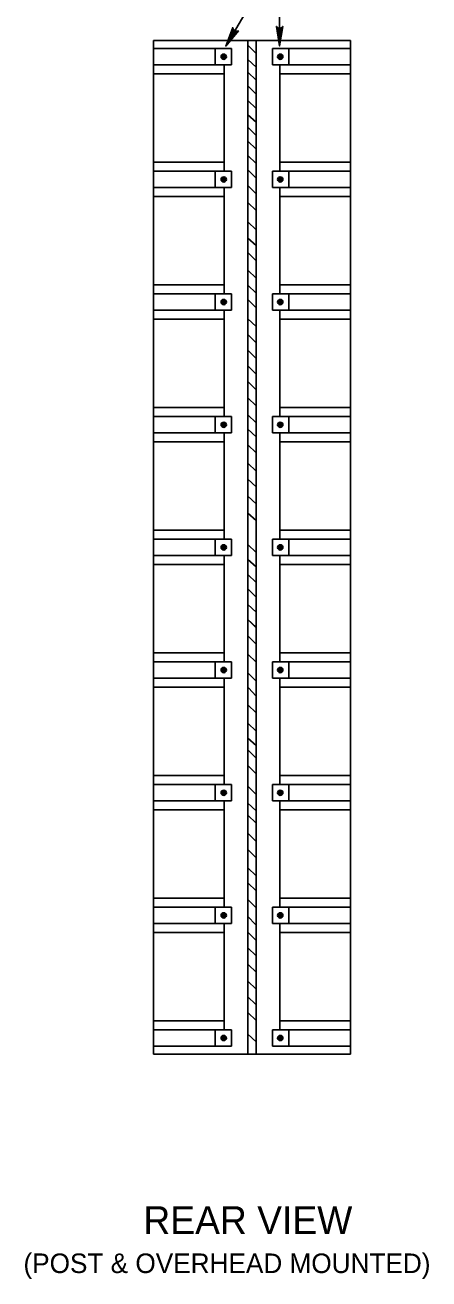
# Model space of a CAD drawing. Extents: x 650495 to 652241, y 298458 to 299646.
# Drawn here: x 650987.1 to 651049.5, y 299351.4 to 299545.2 of the extents above; entities that cross this region are included whole.
import ezdxf

# ---------------------------------------------------------------- set-up
doc = ezdxf.new("R2010")
doc.units = 0
doc.layers.add('2', color=7, linetype='Continuous')
doc.layers.add('3', color=7, linetype='Continuous')

# ---------------------------------------------------------------- blocks, each defined once
blk = doc.blocks.new('RARROW')
at = {"layer": '3'}
blk.add_lwpolyline([(-2.2695, 0.285), (-2.184875, 0.12075), (0, 0), (-2.2695, 0.285), (-2.38575, 0.384625), (0, 0), (-2.183125, -0.108), (-2.262875, -0.2705), (0, 0), (-2.38575, -0.379125), (-2.262875, -0.2705)], dxfattribs=at)

msp = doc.modelspace()

# ---------------------------------------------------------------- linework, layer by layer
at = {"layer": '2'}
for p, q in [((651026.41, 299556.11), (651018.09, 299541.93)), ((651026.41, 299556.11), (651026.4, 299541.95)), ((651006.95, 299386.13), (651006.95, 299542.76)), ((651006.95, 299542.76), (651037.34, 299542.76)), ((651021.52, 299386.13), (651021.52, 299542.76)), ((651022.78, 299540.79), (651021.52, 299542.05)), ((651022.78, 299386.13), (651022.78, 299542.76)), ((651037.34, 299386.13), (651037.34, 299542.76)), ((651017.72, 299541.53), (651006.95, 299541.53)), ((651019, 299541.53), (651016.48, 299541.53)), ((651016.48, 299541.53), (651016.48, 299539.01)), ((651019, 299539.01), (651019, 299541.53)), ((651025.29, 299539.01), (651025.29, 299541.53)), ((651025.29, 299541.53), (651027.81, 299541.53)), ((651026.58, 299541.53), (651037.34, 299541.53)), ((651027.81, 299541.53), (651027.81, 299539.01)), ((651017.72, 299539.01), (651006.95, 299539.01)), ((651016.48, 299539.01), (651019, 299539.01)), ((651017.84, 299522.57), (651017.84, 299539.01)), ((651022.78, 299538.66), (651021.52, 299539.83)), ((651027.81, 299539.01), (651025.29, 299539.01)), ((651026.45, 299522.57), (651026.45, 299539.01)), ((651026.58, 299539.01), (651037.34, 299539.01)), ((651017.84, 299537.61), (651006.95, 299537.61)), ((651022.78, 299536.63), (651021.52, 299537.89)), ((651026.45, 299537.61), (651037.34, 299537.61)), ((651022.78, 299534.5), (651021.52, 299535.76)), ((651022.78, 299532.28), (651021.52, 299533.53)), ((651022.78, 299532.28), (651021.52, 299533.53)), ((651022.78, 299530.15), (651021.52, 299531.31)), ((651022.78, 299528.11), (651021.52, 299529.37)), ((651022.78, 299525.98), (651021.52, 299527.24)), ((651022.78, 299523.76), (651021.52, 299525.02)), ((651017.84, 299523.97), (651006.95, 299523.97)), ((651022.78, 299521.53), (651021.52, 299522.79)), ((651026.45, 299523.97), (651037.34, 299523.97)), ((651017.72, 299522.57), (651006.95, 299522.57)), ((651019, 299522.57), (651016.48, 299522.57)), ((651016.48, 299522.57), (651016.48, 299520.05)), ((651019, 299520.05), (651019, 299522.57)), ((651025.29, 299520.05), (651025.29, 299522.57)), ((651025.29, 299522.57), (651027.81, 299522.57)), ((651026.58, 299522.57), (651037.34, 299522.57)), ((651027.81, 299522.57), (651027.81, 299520.05)), ((651017.72, 299520.05), (651006.95, 299520.05)), ((651016.48, 299520.05), (651019, 299520.05)), ((651017.84, 299503.61), (651017.84, 299520.05)), ((651022.78, 299519.11), (651021.52, 299520.37)), ((651027.81, 299520.05), (651025.29, 299520.05)), ((651026.45, 299503.61), (651026.45, 299520.05)), ((651026.58, 299520.05), (651037.34, 299520.05)), ((651017.84, 299518.66), (651006.95, 299518.66)), ((651022.78, 299516.5), (651021.52, 299517.76)), ((651026.45, 299518.66), (651037.34, 299518.66)), ((651022.78, 299513.5), (651021.52, 299514.75)), ((651022.78, 299511.08), (651021.52, 299512.24)), ((651022.78, 299508.75), (651021.52, 299510.01)), ((651022.78, 299506.04), (651021.52, 299507.3)), ((651017.84, 299505.01), (651006.95, 299505.01)), ((651017.72, 299503.61), (651006.95, 299503.61)), ((651019, 299503.61), (651016.48, 299503.61)), ((651016.48, 299503.61), (651016.48, 299501.1)), ((651019, 299501.1), (651019, 299503.61)), ((651022.78, 299503.72), (651021.52, 299504.98)), ((651025.29, 299501.1), (651025.29, 299503.61)), ((651025.29, 299503.61), (651027.81, 299503.61)), ((651026.45, 299505.01), (651037.34, 299505.01)), ((651026.58, 299503.61), (651037.34, 299503.61)), ((651027.81, 299503.61), (651027.81, 299501.1)), ((651022.78, 299501.49), (651021.52, 299502.75)), ((651017.72, 299501.1), (651006.95, 299501.1)), ((651017.84, 299499.7), (651006.95, 299499.7)), ((651016.48, 299501.1), (651019, 299501.1)), ((651017.84, 299484.66), (651017.84, 299501.1)), ((651022.78, 299498.59), (651021.52, 299499.75)), ((651027.81, 299501.1), (651025.29, 299501.1)), ((651026.45, 299484.66), (651026.45, 299501.1)), ((651026.45, 299499.7), (651037.34, 299499.7)), ((651026.58, 299501.1), (651037.34, 299501.1)), ((651022.78, 299496.07), (651021.52, 299497.33)), ((651022.78, 299493.65), (651021.52, 299494.91)), ((651022.78, 299491.23), (651021.52, 299492.49)), ((651022.78, 299488.81), (651021.52, 299490.07)), ((651017.84, 299486.06), (651006.95, 299486.06)), ((651022.78, 299486.3), (651021.52, 299487.55)), ((651026.45, 299486.06), (651037.34, 299486.06)), ((651017.72, 299484.66), (651006.95, 299484.66)), ((651019, 299484.66), (651016.48, 299484.66)), ((651016.48, 299484.66), (651016.48, 299482.14)), ((651019, 299482.14), (651019, 299484.66)), ((651022.78, 299483.68), (651021.52, 299484.94)), ((651025.29, 299482.14), (651025.29, 299484.66)), ((651025.29, 299484.66), (651027.81, 299484.66)), ((651026.58, 299484.66), (651037.34, 299484.66)), ((651027.81, 299484.66), (651027.81, 299482.14)), ((651017.72, 299482.14), (651006.95, 299482.14)), ((651016.48, 299482.14), (651019, 299482.14)), ((651017.84, 299465.7), (651017.84, 299482.14)), ((651022.78, 299481.55), (651021.52, 299482.71)), ((651027.81, 299482.14), (651025.29, 299482.14)), ((651026.45, 299465.7), (651026.45, 299482.14)), ((651026.58, 299482.14), (651037.34, 299482.14)), ((651017.84, 299480.75), (651006.95, 299480.75)), ((651022.78, 299479.04), (651021.52, 299480.29)), ((651026.45, 299480.75), (651037.34, 299480.75)), ((651022.78, 299476.23), (651021.52, 299477.49)), ((651022.78, 299473.81), (651021.52, 299474.97)), ((651022.78, 299471.19), (651021.52, 299472.36)), ((651022.78, 299468.58), (651021.52, 299469.74)), ((651017.84, 299467.1), (651006.95, 299467.1)), ((651026.45, 299467.1), (651037.34, 299467.1)), ((651017.72, 299465.7), (651006.95, 299465.7)), ((651019, 299465.7), (651016.48, 299465.7)), ((651016.48, 299465.7), (651016.48, 299463.19)), ((651019, 299463.19), (651019, 299465.7)), ((651022.78, 299463.64), (651021.52, 299464.9)), ((651025.29, 299463.19), (651025.29, 299465.7)), ((651025.29, 299465.7), (651027.81, 299465.7)), ((651026.58, 299465.7), (651037.34, 299465.7)), ((651027.81, 299465.7), (651027.81, 299463.19)), ((651017.72, 299463.19), (651006.95, 299463.19)), ((651016.48, 299463.19), (651019, 299463.19)), ((651017.84, 299463.19), (651017.84, 299446.75)), ((651027.81, 299463.19), (651025.29, 299463.19)), ((651026.45, 299463.19), (651026.45, 299446.75)), ((651026.58, 299463.19), (651037.34, 299463.19)), ((651017.84, 299461.79), (651006.95, 299461.79)), ((651022.78, 299461.42), (651021.52, 299462.58)), ((651026.45, 299461.79), (651037.34, 299461.79)), ((651022.78, 299459), (651021.52, 299460.26)), ((651022.78, 299456.77), (651021.52, 299458.03)), ((651022.78, 299454.45), (651021.52, 299455.61)), ((651022.68, 299452.13), (651021.52, 299453.29)), ((651022.78, 299452.13), (651021.52, 299453.29)), ((651022.78, 299449.51), (651021.52, 299450.77)), ((651017.84, 299448.15), (651006.95, 299448.15)), ((651022.78, 299446.7), (651021.52, 299447.96)), ((651026.45, 299448.15), (651037.34, 299448.15)), ((651017.72, 299446.75), (651006.95, 299446.75)), ((651019, 299446.75), (651016.48, 299446.75)), ((651016.48, 299446.75), (651016.48, 299444.23)), ((651019, 299444.23), (651019, 299446.75)), ((651025.29, 299444.23), (651025.29, 299446.75)), ((651025.29, 299446.75), (651027.81, 299446.75)), ((651026.58, 299446.75), (651037.34, 299446.75)), ((651027.81, 299446.75), (651027.81, 299444.23)), ((651017.72, 299444.23), (651006.95, 299444.23)), ((651016.48, 299444.23), (651019, 299444.23)), ((651017.84, 299427.79), (651017.84, 299444.23)), ((651022.78, 299443.8), (651021.52, 299445.06)), ((651027.81, 299444.23), (651025.29, 299444.23)), ((651026.45, 299427.79), (651026.45, 299444.23)), ((651026.58, 299444.23), (651037.34, 299444.23)), ((651017.84, 299442.83), (651006.95, 299442.83)), ((651022.78, 299441.48), (651021.61, 299442.74)), ((651026.45, 299442.83), (651037.34, 299442.83)), ((651022.78, 299438.86), (651021.52, 299440.12)), ((651022.78, 299436.06), (651021.52, 299437.31)), ((651022.78, 299433.83), (651021.52, 299434.99)), ((651022.78, 299431.89), (651021.52, 299433.15)), ((651022.78, 299429.47), (651021.52, 299430.73)), ((651017.84, 299429.19), (651006.95, 299429.19)), ((651017.72, 299427.79), (651006.95, 299427.79)), ((651019, 299427.79), (651016.48, 299427.79)), ((651016.48, 299427.79), (651016.48, 299425.28)), ((651019, 299425.28), (651019, 299427.79)), ((651025.29, 299425.28), (651025.29, 299427.79)), ((651025.29, 299427.79), (651027.81, 299427.79)), ((651026.45, 299429.19), (651037.34, 299429.19)), ((651026.58, 299427.79), (651037.34, 299427.79)), ((651027.81, 299427.79), (651027.81, 299425.28)), ((651022.78, 299426.28), (651021.52, 299427.54)), ((651017.72, 299425.28), (651006.95, 299425.28)), ((651017.84, 299423.88), (651006.95, 299423.88)), ((651016.48, 299425.28), (651019, 299425.28)), ((651017.84, 299408.84), (651017.84, 299425.28)), ((651022.78, 299423.76), (651021.52, 299424.92)), ((651027.81, 299425.28), (651025.29, 299425.28)), ((651026.45, 299408.84), (651026.45, 299425.28)), ((651026.45, 299423.88), (651037.34, 299423.88)), ((651026.58, 299425.28), (651037.34, 299425.28)), ((651022.78, 299421.83), (651021.52, 299423.09)), ((651022.78, 299419.02), (651021.52, 299420.28)), ((651022.78, 299416.5), (651021.52, 299417.76)), ((651022.78, 299413.7), (651021.52, 299414.95)), ((651022.78, 299411.37), (651021.52, 299412.63)), ((651017.84, 299410.24), (651006.95, 299410.24)), ((651017.72, 299408.84), (651006.95, 299408.84)), ((651019, 299408.84), (651016.48, 299408.84)), ((651016.48, 299408.84), (651016.48, 299406.32)), ((651019, 299406.32), (651019, 299408.84)), ((651022.78, 299408.76), (651021.52, 299410.02)), ((651025.29, 299406.32), (651025.29, 299408.84)), ((651025.29, 299408.84), (651027.81, 299408.84)), ((651026.45, 299410.24), (651037.34, 299410.24)), ((651026.58, 299408.84), (651037.34, 299408.84)), ((651027.81, 299408.84), (651027.81, 299406.32)), ((651022.68, 299406.15), (651021.52, 299407.4)), ((651017.72, 299406.32), (651006.95, 299406.32)), ((651017.84, 299404.92), (651006.95, 299404.92)), ((651016.48, 299406.32), (651019, 299406.32)), ((651017.84, 299389.88), (651017.84, 299406.32)), ((651022.68, 299403.82), (651021.52, 299404.98)), ((651027.81, 299406.32), (651025.29, 299406.32)), ((651026.45, 299389.88), (651026.45, 299406.32)), ((651026.45, 299404.92), (651037.34, 299404.92)), ((651026.58, 299406.32), (651037.34, 299406.32)), ((651022.78, 299401.31), (651021.52, 299402.56)), ((651022.78, 299398.79), (651021.61, 299399.95)), ((651022.78, 299396.17), (651021.52, 299397.43)), ((651022.68, 299393.85), (651021.52, 299395.01)), ((651017.84, 299391.28), (651006.95, 299391.28)), ((651022.78, 299391.33), (651021.52, 299392.59)), ((651026.45, 299391.28), (651037.34, 299391.28)), ((651017.72, 299389.88), (651006.95, 299389.88)), ((651016.48, 299389.88), (651019, 299389.88)), ((651016.48, 299387.37), (651016.48, 299389.88)), ((651017.74, 299389.88), (651017.74, 299389.88)), ((651019, 299389.88), (651019, 299387.37)), ((651022.78, 299388.04), (651021.52, 299389.21)), ((651027.81, 299389.88), (651025.29, 299389.88)), ((651025.29, 299389.88), (651025.29, 299387.37)), ((651026.55, 299389.88), (651026.55, 299389.88)), ((651026.58, 299389.88), (651037.34, 299389.88)), ((651027.81, 299387.37), (651027.81, 299389.88)), ((651017.72, 299387.37), (651006.95, 299387.37)), ((651019, 299387.37), (651016.48, 299387.37)), ((651025.29, 299387.37), (651027.81, 299387.37)), ((651026.58, 299387.37), (651037.34, 299387.37)), ((651006.95, 299386.13), (651037.34, 299386.13))]:
    msp.add_line(p, q, dxfattribs=at)
for points in [[(651017.65, 299539.98), (651017.55, 299540.27), (651017.55, 299540.46), (651017.74, 299540.56), (651017.94, 299540.46), (651018.03, 299540.36), (651018.03, 299540.07), (651017.94, 299539.98), (651017.74, 299539.98), (651017.65, 299540.27), (651017.65, 299540.36), (651017.65, 299540.46), (651017.74, 299540.46), (651017.84, 299540.36), (651017.94, 299540.27), (651017.94, 299540.07), (651017.84, 299540.17), (651017.74, 299540.36)], [(651026.65, 299539.98), (651026.75, 299540.27), (651026.75, 299540.46), (651026.55, 299540.56), (651026.36, 299540.46), (651026.26, 299540.36), (651026.26, 299540.07), (651026.36, 299539.98), (651026.55, 299539.98), (651026.65, 299540.27), (651026.65, 299540.36), (651026.65, 299540.46), (651026.55, 299540.46), (651026.45, 299540.36), (651026.36, 299540.27), (651026.36, 299540.07), (651026.45, 299540.17), (651026.55, 299540.36)], [(651017.65, 299521.02), (651017.55, 299521.31), (651017.55, 299521.51), (651017.74, 299521.6), (651017.94, 299521.51), (651018.03, 299521.41), (651018.03, 299521.12), (651017.94, 299521.02), (651017.74, 299521.02), (651017.65, 299521.31), (651017.65, 299521.41), (651017.65, 299521.51), (651017.74, 299521.51), (651017.84, 299521.41), (651017.94, 299521.31), (651017.94, 299521.12), (651017.84, 299521.22), (651017.74, 299521.41)], [(651026.65, 299521.02), (651026.75, 299521.31), (651026.75, 299521.51), (651026.55, 299521.6), (651026.36, 299521.51), (651026.26, 299521.41), (651026.26, 299521.12), (651026.36, 299521.02), (651026.55, 299521.02), (651026.65, 299521.31), (651026.65, 299521.41), (651026.65, 299521.51), (651026.55, 299521.51), (651026.45, 299521.41), (651026.36, 299521.31), (651026.36, 299521.12), (651026.45, 299521.22), (651026.55, 299521.41)], [(651017.65, 299502.07), (651017.55, 299502.36), (651017.55, 299502.55), (651017.74, 299502.65), (651017.94, 299502.55), (651018.03, 299502.45), (651018.03, 299502.16), (651017.94, 299502.07), (651017.74, 299502.07), (651017.65, 299502.36), (651017.65, 299502.45), (651017.65, 299502.55), (651017.74, 299502.55), (651017.84, 299502.45), (651017.94, 299502.36), (651017.94, 299502.16), (651017.84, 299502.26), (651017.74, 299502.45)], [(651026.65, 299502.07), (651026.75, 299502.36), (651026.75, 299502.55), (651026.55, 299502.65), (651026.36, 299502.55), (651026.26, 299502.45), (651026.26, 299502.16), (651026.36, 299502.07), (651026.55, 299502.07), (651026.65, 299502.36), (651026.65, 299502.45), (651026.65, 299502.55), (651026.55, 299502.55), (651026.45, 299502.45), (651026.36, 299502.36), (651026.36, 299502.16), (651026.45, 299502.26), (651026.55, 299502.45)], [(651017.65, 299483.11), (651017.55, 299483.4), (651017.55, 299483.59), (651017.74, 299483.69), (651017.94, 299483.59), (651018.03, 299483.5), (651018.03, 299483.21), (651017.94, 299483.11), (651017.74, 299483.11), (651017.65, 299483.4), (651017.65, 299483.5), (651017.65, 299483.59), (651017.74, 299483.59), (651017.84, 299483.5), (651017.94, 299483.4), (651017.94, 299483.21), (651017.84, 299483.3), (651017.74, 299483.5)], [(651026.65, 299483.11), (651026.75, 299483.4), (651026.75, 299483.59), (651026.55, 299483.69), (651026.36, 299483.59), (651026.26, 299483.5), (651026.26, 299483.21), (651026.36, 299483.11), (651026.55, 299483.11), (651026.65, 299483.4), (651026.65, 299483.5), (651026.65, 299483.59), (651026.55, 299483.59), (651026.45, 299483.5), (651026.36, 299483.4), (651026.36, 299483.21), (651026.45, 299483.3), (651026.55, 299483.5)], [(651017.65, 299464.16), (651017.55, 299464.45), (651017.55, 299464.64), (651017.74, 299464.74), (651017.94, 299464.64), (651018.03, 299464.54), (651018.03, 299464.25), (651017.94, 299464.16), (651017.74, 299464.16), (651017.65, 299464.45), (651017.65, 299464.54), (651017.65, 299464.64), (651017.74, 299464.64), (651017.84, 299464.54), (651017.94, 299464.45), (651017.94, 299464.25), (651017.84, 299464.35), (651017.74, 299464.54)], [(651026.65, 299464.16), (651026.75, 299464.45), (651026.75, 299464.64), (651026.55, 299464.74), (651026.36, 299464.64), (651026.26, 299464.54), (651026.26, 299464.25), (651026.36, 299464.16), (651026.55, 299464.16), (651026.65, 299464.45), (651026.65, 299464.54), (651026.65, 299464.64), (651026.55, 299464.64), (651026.45, 299464.54), (651026.36, 299464.45), (651026.36, 299464.25), (651026.45, 299464.35), (651026.55, 299464.54)], [(651017.65, 299445.2), (651017.55, 299445.49), (651017.55, 299445.68), (651017.74, 299445.78), (651017.94, 299445.68), (651018.03, 299445.59), (651018.03, 299445.3), (651017.94, 299445.2), (651017.74, 299445.2), (651017.65, 299445.49), (651017.65, 299445.59), (651017.65, 299445.68), (651017.74, 299445.68), (651017.84, 299445.59), (651017.94, 299445.49), (651017.94, 299445.3), (651017.84, 299445.39), (651017.74, 299445.59)], [(651026.65, 299445.2), (651026.75, 299445.49), (651026.75, 299445.68), (651026.55, 299445.78), (651026.36, 299445.68), (651026.26, 299445.59), (651026.26, 299445.3), (651026.36, 299445.2), (651026.55, 299445.2), (651026.65, 299445.49), (651026.65, 299445.59), (651026.65, 299445.68), (651026.55, 299445.68), (651026.45, 299445.59), (651026.36, 299445.49), (651026.36, 299445.3), (651026.45, 299445.39), (651026.55, 299445.59)], [(651017.65, 299426.24), (651017.55, 299426.54), (651017.55, 299426.73), (651017.74, 299426.83), (651017.94, 299426.73), (651018.03, 299426.63), (651018.03, 299426.34), (651017.94, 299426.24), (651017.74, 299426.24), (651017.65, 299426.54), (651017.65, 299426.63), (651017.65, 299426.73), (651017.74, 299426.73), (651017.84, 299426.63), (651017.94, 299426.54), (651017.94, 299426.34), (651017.84, 299426.44), (651017.74, 299426.63)], [(651026.65, 299426.24), (651026.75, 299426.54), (651026.75, 299426.73), (651026.55, 299426.83), (651026.36, 299426.73), (651026.26, 299426.63), (651026.26, 299426.34), (651026.36, 299426.24), (651026.55, 299426.24), (651026.65, 299426.54), (651026.65, 299426.63), (651026.65, 299426.73), (651026.55, 299426.73), (651026.45, 299426.63), (651026.36, 299426.54), (651026.36, 299426.34), (651026.45, 299426.44), (651026.55, 299426.63)], [(651017.65, 299407.29), (651017.55, 299407.58), (651017.55, 299407.77), (651017.74, 299407.87), (651017.94, 299407.77), (651018.03, 299407.68), (651018.03, 299407.39), (651017.94, 299407.29), (651017.74, 299407.29), (651017.65, 299407.58), (651017.65, 299407.68), (651017.65, 299407.77), (651017.74, 299407.77), (651017.84, 299407.68), (651017.94, 299407.58), (651017.94, 299407.39), (651017.84, 299407.48), (651017.74, 299407.68)], [(651026.65, 299407.29), (651026.75, 299407.58), (651026.75, 299407.77), (651026.55, 299407.87), (651026.36, 299407.77), (651026.26, 299407.68), (651026.26, 299407.39), (651026.36, 299407.29), (651026.55, 299407.29), (651026.65, 299407.58), (651026.65, 299407.68), (651026.65, 299407.77), (651026.55, 299407.77), (651026.45, 299407.68), (651026.36, 299407.58), (651026.36, 299407.39), (651026.45, 299407.48), (651026.55, 299407.68)], [(651017.65, 299388.91), (651017.55, 299388.62), (651017.55, 299388.43), (651017.74, 299388.33), (651017.94, 299388.43), (651018.03, 299388.53), (651018.03, 299388.82), (651017.94, 299388.91), (651017.74, 299388.91), (651017.65, 299388.62), (651017.65, 299388.53), (651017.65, 299388.43), (651017.74, 299388.43), (651017.84, 299388.53), (651017.94, 299388.62), (651017.94, 299388.82), (651017.84, 299388.72), (651017.74, 299388.53)], [(651026.65, 299388.91), (651026.75, 299388.62), (651026.75, 299388.43), (651026.55, 299388.33), (651026.36, 299388.43), (651026.26, 299388.53), (651026.26, 299388.82), (651026.36, 299388.91), (651026.55, 299388.91), (651026.65, 299388.62), (651026.65, 299388.53), (651026.65, 299388.43), (651026.55, 299388.43), (651026.45, 299388.53), (651026.36, 299388.62), (651026.36, 299388.82), (651026.45, 299388.72), (651026.55, 299388.53)]]:
    msp.add_lwpolyline(points, dxfattribs=at)
for centre in [(651017.78, 299540.27), (651026.51, 299540.27), (651017.78, 299521.31), (651026.51, 299521.31), (651017.78, 299502.36), (651026.51, 299502.36), (651017.78, 299483.4), (651026.51, 299483.4), (651017.78, 299464.45), (651026.51, 299464.45), (651017.78, 299445.49), (651026.51, 299445.49), (651017.78, 299426.53), (651026.51, 299426.53), (651017.78, 299407.58), (651026.51, 299407.58), (651017.78, 299388.63), (651026.51, 299388.63)]:
    msp.add_circle(centre, 0.407, dxfattribs=at)

# ---------------------------------------------------------------- block references
at = {"layer": '2', "yscale": 1.3092961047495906}
for p, xscale, rotation in [((651018.09, 299541.93), 1.257434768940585, -120.29357719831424), ((651026.4, 299541.95), 1.2574347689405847, -90.00000000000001)]:
    msp.add_blockref('RARROW', p, dxfattribs=dict(at, xscale=xscale, rotation=rotation))

# ---------------------------------------------------------------- texts
at = {"layer": '2'}
for s, height, p in [('REAR VIEW', 4.3, (651005.37, 299358.34)), ('(POST & OVERHEAD MOUNTED)', 3.0217, (650986.85, 299352.31))]:
    msp.add_text(s, height=height, dxfattribs=at).set_placement(p)

doc.saveas('drawing.dxf')
